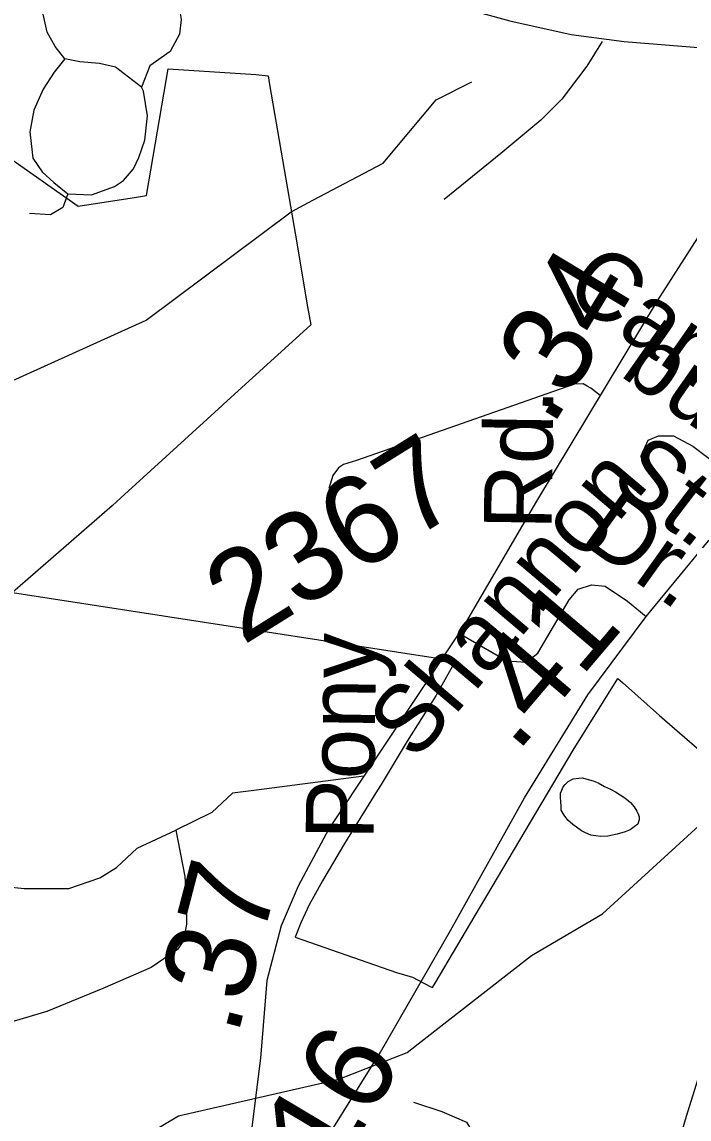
# Model space of a CAD drawing. Extents: x 2001466 to 31450019, y -30647475 to 847247.
# Drawn here: x 2197224 to 2199091, y 751164 to 754237 of the extents above; entities that cross this region are included whole.
import ezdxf

# ---------------------------------------------------------------- set-up
doc = ezdxf.new("R2010")
doc.units = 0
for name, color, linetype in [('Exist Boundary Political City Limit New', 7, 'Continuous'), ('Exist Hydrographic Misc Water Feature', 7, 'Continuous'), ('Exist Railroad Mainline', 7, 'Continuous'), ('Exist Road Non-System Type 51', 7, 'Continuous'), ('Exist Road Non-System Type 51 Label', 7, 'Continuous'), ('Exist Road Primary NC Attributed', 7, 'Continuous'), ('Exist Road Primary US Attributed', 7, 'Continuous'), ('Exist Road Primary US Mileage Hundredths English Label', 7, 'Continuous'), ('Exist Road Secondary Mileage Hundredths English Label', 7, 'Continuous'), ('Exist Road Secondary Type 51 Attributed', 7, 'Continuous'), ('Exist Road Secondary Type 51 Label', 7, 'Continuous'), ('Exist Road Secondary Type 51 Number Label', 7, 'Continuous'), ('Map Preparation Boundary City Limit Buffer Line', 7, 'Continuous')]:
    doc.layers.add(name, color=color, linetype=linetype)

msp = doc.modelspace()

# ---------------------------------------------------------------- linework, layer by layer
at = {"layer": 'Exist Boundary Political City Limit New'}
msp.add_lwpolyline([(2196951.2, 754023.1), (2197381, 753721.6), (2197544, 753746.4), (2197572.2, 753750.7), (2197615.2, 754002.6), (2197632.8, 754105.9), (2197878.5, 754090.1), (2197912.8, 754086.4), (2197917, 754062), (2197989, 753639.5), (2198023, 753439.3), (2198032, 753388.7), (2198020.8, 753378.4), (2197788, 753166.9), (2197783.8, 753163.1), (2197500, 752904.4), (2197476.5, 752881.3), (2197197.2, 752638.6), (2198374.8, 752457.2), (2198437.5, 752447.5), (2198381.8, 752349.7), (2198302.2, 752222.5), (2198228.8, 752101.2), (2198219, 752085.5), (2198133.8, 751948.4), (2198123.8, 751931.4), (2198065, 751831.2), (2198040.5, 751787), (2198027.8, 751763.9), (2198004, 751713.4), (2197988.8, 751673.2), (2198272.5, 751574.9), (2198316.5, 751561.1), (2198368, 751534.9), (2198372.5, 751532.5), (2198380.2, 751544.9), (2198492.2, 751734.3), (2198710, 752101.1), (2198767, 752197), (2198891.5, 752398.2), (2198904.5, 752386.8), (2199008.5, 752294.8), (2199176.5, 752149.2)], dxfattribs=at)
at = {"layer": 'Exist Hydrographic Misc Water Feature'}
msp.add_line((2198333.2, 751374.6), (2198341.4, 751381), dxfattribs=at)
for points in [[(2198038.3, 753737.8), (2198234.8, 753841.3), (2198382.9, 754018.6), (2198482.9, 754069.1)], [(2193961.9, 751278.4), (2194127.8, 751412.8), (2194292.9, 751698.1), (2194956.9, 751953.5), (2195996.9, 752211), (2196146, 752286.6), (2196236.8, 752402.9), (2196425.8, 752779.5), (2196516.9, 752879.3), (2196599.9, 752930.1), (2196823.9, 752964.8), (2196974, 753050.3), (2197147.8, 753210.8), (2197570.9, 753402.2), (2197976.9, 753705.5), (2198038.3, 753737.8)], [(2198341.4, 751381), (2198649.8, 751621.8), (2198848.9, 751739.2), (2199378.8, 752223.6), (2199559, 752271)], [(2198870.9, 752088.1), (2198884.8, 752080.3), (2198911.1, 752064.1), (2198927.1, 752050.4), (2198937.3, 752038.7), (2198945.1, 752026.6), (2198949.4, 752016.6), (2198951.5, 752010.6), (2198951.9, 752002.4), (2198949.6, 751996.7), (2198947.6, 751990.5), (2198937.3, 751982.3), (2198925.8, 751974.3), (2198912.1, 751968.3), (2198890, 751962.3), (2198863.7, 751956.1), (2198843.8, 751955.9), (2198830.1, 751957.6), (2198815.9, 751959.7), (2198801.6, 751965.5), (2198789.9, 751971.4), (2198765.5, 751989.2), (2198751.3, 752001.1), (2198741.9, 752015.1), (2198733.1, 752029), (2198733.5, 752039.1), (2198731.7, 752053.1), (2198731, 752065), (2198730.8, 752077.2), (2198735.1, 752085.1), (2198739, 752095), (2198744.6, 752101.1), (2198752.8, 752109.2), (2198766.9, 752117.2), (2198782.9, 752119.2), (2198792.8, 752119.4), (2198802.6, 752117.5), (2198822.9, 752111.6), (2198836.9, 752105.8), (2198854.7, 752095.8), (2198870.9, 752088.1)], [(2193773.9, 749638.9), (2193898, 749688.9), (2194322.8, 749716.2), (2194731.9, 749602.9), (2194980.8, 749653.5), (2195255.8, 749739.7), (2195546.8, 749733.8), (2195671.9, 749816.5), (2195786.9, 750017.5), (2195901.9, 750300.5), (2196091.8, 750503.3), (2196349.8, 750530.8), (2196456.8, 750613.9), (2196522.8, 750724), (2196671.9, 750881.8), (2196804.8, 750967.6), (2196962.9, 751026.7), (2197380, 751005), (2197661.9, 751173.1), (2198110.8, 751275.4), (2198301.9, 751350.2), (2198333.2, 751374.6)]]:
    msp.add_lwpolyline(points, dxfattribs=at)
at = {"layer": 'Exist Railroad Mainline'}
msp.add_lwpolyline([(2198957.9, 750510.8), (2198980.1, 750666.5), (2199017, 750905.7), (2199045.7, 751041.1), (2199084.4, 751172.3), (2199125.1, 751303.4), (2199173.6, 751426.4), (2199217.4, 751511.5), (2199273.4, 751612.3), (2199331.3, 751703.1), (2199388.7, 751773.9), (2199454.1, 751842.6), (2199517.2, 751897.3), (2199566.1, 751940.3), (2199629, 751983), (2199734.1, 752040.8), (2199760.4, 752055.6), (2199847.4, 752104.5), (2200003.3, 752195.3), (2201147.9, 752837.8), (2201555.4, 753066.6), (2201645.9, 753117.4), (2202458.7, 753554.6), (2202492.8, 753573.2)], dxfattribs=at)
at = {"layer": 'Exist Road Non-System Type 51'}
for points in [[(2197558.1, 754054.8), (2197485.2, 754110.9), (2197440.2, 754120.8), (2197385.5, 754125), (2197343.4, 754133.4), (2197316.8, 754168.5), (2197293.7, 754208.1), (2197283.1, 754259.2), (2197287.3, 754297.1), (2197305.5, 754333.7), (2197347.6, 754380), (2197395.3, 754401.1), (2197438.8, 754399.7), (2197521, 754393.8)], [(2197521, 754393.8), (2197582, 754378.6), (2197625.5, 754354.7), (2197659.2, 754307), (2197669.4, 754244.3), (2197664.8, 754203.1), (2197638.1, 754154.5), (2197582, 754113.8), (2197558.1, 754054.8)], [(2198848.3, 754182.6), (2198804.9, 754113.5), (2198735, 754020.9), (2198675.9, 753962.2), (2198563.9, 753868.5), (2198405.3, 753739.8)], [(2197343.4, 754133.4), (2197314, 754096.9), (2197283.1, 754049.2), (2197256.4, 753990.2), (2197245.2, 753929.8), (2197251.9, 753872)], [(2197507.6, 753793.3), (2197535.7, 753825.6), (2197551.1, 753857.9), (2197568, 753905.6), (2197575, 753974.4), (2197563.9, 754043.2), (2197558.1, 754054.8)], [(2197251.9, 753872), (2197254.1, 753855.2), (2197280.3, 753817.2), (2197312.5, 753787.7), (2197351.8, 753755.4)], [(2197351.8, 753755.4), (2197417.8, 753752.6), (2197482.3, 753776.4), (2197507.6, 753793.3)], [(2197351.8, 753755.4), (2197337.8, 753717.5), (2197303.6, 753697), (2197244.2, 753700.3)], [(2198806.3, 753217.2), (2198794.7, 753223.9), (2198770.6, 753222.4), (2198748.5, 753214.8), (2198160.4, 753008.9), (2198124.1, 752997.7), (2198110, 752988), (2198093.5, 752966.3), (2198082.8, 752930.5)], [(2198842.1, 753190.7), (2198816.4, 753211.4), (2198806.3, 753217.2)], [(2198956, 753019.6), (2198976.8, 753065.5), (2199006, 753078), (2199047.7, 753078), (2199102, 753048.8), (2199269.7, 752922.1)], [(2198448.1, 752524.6), (2198580.6, 752447.8), (2198634.8, 752443.7), (2198668.2, 752468.7), (2198755.8, 752618.9), (2198780.8, 752648.2), (2198818.4, 752660.7), (2198855.9, 752656.5), (2198918.5, 752614.8), (2198970.6, 752572.1)], [(2198180.9, 752124.7), (2197879.9, 752085.6), (2197813.2, 752077.2), (2197754.8, 752023), (2197654.7, 751972.9)], [(2197654.7, 751972.9), (2197679.8, 751843.5), (2197683.9, 751760), (2197683.9, 751710), (2197675.6, 751664), (2197658.9, 751639), (2197585.3, 751589), (2197450.1, 751529.8), (2197292.8, 751465), (2197109.7, 751410.8), (2197031.2, 751391.6)], [(2197050, 751835.2), (2197104.2, 751818.5), (2197150.1, 751818.5), (2197229.3, 751810.1), (2197287.7, 751810.1), (2197354.4, 751810.1), (2197442, 751839.3), (2197487.9, 751868.5), (2197546.3, 751922.8), (2197654.7, 751972.9)], [(2198320, 751211.7), (2198399.1, 751185.3), (2198468.3, 751155.6), (2198544.1, 751027), (2198557.3, 751007.2), (2198543.1, 750898.2)]]:
    msp.add_lwpolyline(points, dxfattribs=at)
at = {"layer": 'Exist Road Primary NC Attributed'}
msp.add_lwpolyline([(2197487.3, 754533.3), (2197747.3, 754463.2), (2197983.8, 754399.3), (2198422.8, 754286.2), (2198589.2, 754240.1), (2198760.8, 754202.4), (2198909.9, 754182.5), (2199128.6, 754164.7), (2199412.1, 754159.5)], dxfattribs=at)
at = {"layer": 'Exist Road Primary US Attributed'}
msp.add_lwpolyline([(2197822.1, 750673.6), (2197914.2, 750846.4), (2198013.6, 751007.7), (2198227.6, 751351.1), (2198423.3, 751692.5), (2198630, 752064.2), (2198807.8, 752352.2), (2198970.6, 752572.1), (2199145.3, 752783.6), (2199494.3, 753172.1)], dxfattribs=at)
at = {"layer": 'Exist Road Secondary Type 51 Attributed'}
msp.add_lwpolyline([(2199348.6, 753984.6), (2199204.2, 753772.1), (2199001.7, 753455.8), (2198663.7, 752894.6), (2198458.6, 752542.7), (2198083, 751977.3), (2197997.2, 751816), (2197949, 751705), (2197909.3, 751552.2), (2197891.5, 751334.4), (2197845.4, 750970), (2197822.1, 750673.6)], dxfattribs=at)
at = {"layer": 'Map Preparation Boundary City Limit Buffer Line'}
msp.add_lwpolyline([(2196951.2, 754023.1), (2197381, 753721.6), (2197544, 753746.4), (2197572.2, 753750.7), (2197615.2, 754002.6), (2197632.8, 754105.9), (2197878.5, 754090.1), (2197912.8, 754086.4), (2197917, 754062), (2197989, 753639.5), (2198023, 753439.3), (2198032, 753388.7), (2198020.8, 753378.4), (2197788, 753166.9), (2197783.8, 753163.1), (2197500, 752904.4), (2197476.5, 752881.3), (2197197.2, 752638.6), (2198374.8, 752457.2), (2198437.5, 752447.5), (2198381.8, 752349.7), (2198302.2, 752222.5), (2198228.8, 752101.2), (2198219, 752085.5), (2198133.8, 751948.4), (2198123.8, 751931.4), (2198065, 751831.2), (2198040.5, 751787), (2198027.8, 751763.9), (2198004, 751713.4), (2197988.8, 751673.2), (2198272.5, 751574.9), (2198316.5, 751561.1), (2198368, 751534.9), (2198372.5, 751532.5), (2198380.2, 751544.9), (2198492.2, 751734.3), (2198710, 752101.1), (2198767, 752197), (2198891.5, 752398.2), (2198904.5, 752386.8), (2199008.5, 752294.8), (2199176.5, 752149.2)], dxfattribs=at)

# ---------------------------------------------------------------- texts
at = {"layer": 'Exist Road Non-System Type 51 Label'}
for s, rotation, p in [('Canter-', 325.019, (2198734.2, 753471.9)), ('bury', 325.019, (2198893.4, 753248.6)), ('St.', 322.7147, (2198864.6, 752944.2)), ('Shannon', 49.7929, (2198325, 752162.7)), ('Dr.', 324.5147, (2198782.1, 752782.2))]:
    msp.add_text(s, height=190, rotation=rotation, dxfattribs=at).set_placement(p)
at = {"layer": 'Exist Road Primary US Mileage Hundredths English Label'}
for s, rotation, p in [('.41', 49.6516, (2198608, 752186.5)), ('.16', 59.1387, (2198052.8, 750923.8))]:
    msp.add_text(s, height=250, rotation=rotation, dxfattribs=at).set_placement(p)
at = {"layer": 'Exist Road Secondary Mileage Hundredths English Label'}
for s, rotation, p in [('.34', 58.9442, (2198706.6, 753099.1)), ('.37', 75.4209, (2197826.4, 751392.9))]:
    msp.add_text(s, height=250, rotation=rotation, dxfattribs=at).set_placement(p)
at = {"layer": 'Exist Road Secondary Type 51 Label'}
for s, p in [('Rd.', (2198706.3, 752813.6)), ('Pony', (2198207.6, 751945.1))]:
    msp.add_text(s, height=190, rotation=89.2141, dxfattribs=at).set_placement(p)
at = {"layer": 'Exist Road Secondary Type 51 Number Label'}
msp.add_text('2367', height=250, rotation=31.918, dxfattribs=at).set_placement((2197841.6, 752489.3))

doc.saveas('drawing.dxf')
